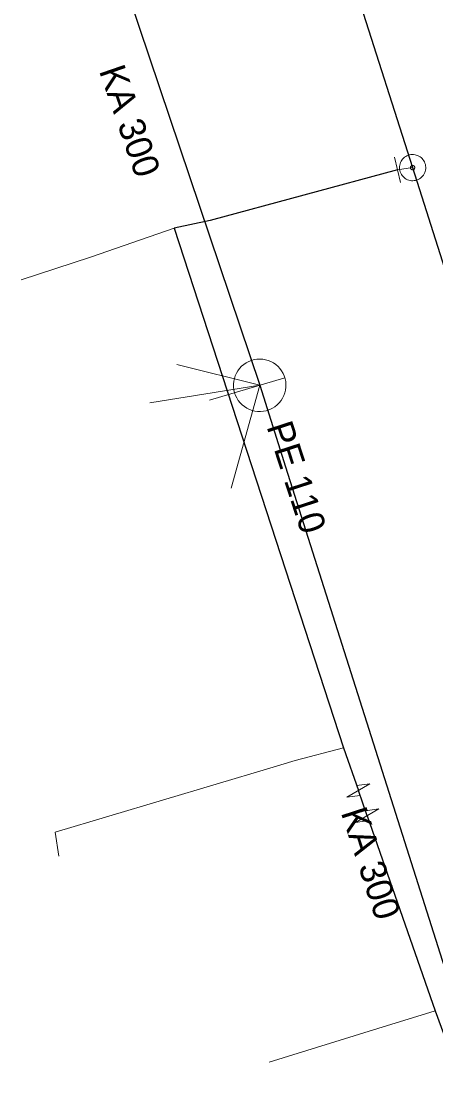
# Model space of a CAD drawing. Extents: x -807203 to -805207, y -993656 to -992505.
# Drawn here: x -807119.4 to -807103.6, y -993130.79 to -993090.44 of the extents above; entities that cross this region are included whole.
import ezdxf

# ---------------------------------------------------------------- set-up
doc = ezdxf.new("R2010")
doc.units = 0
doc.header["$LTSCALE"] = 0.4
for name, color, linetype, lineweight in [('1', 7, 'Continuous', 13), ('11', 7, 'Continuous', 13), ('13', 7, 'Continuous', 13), ('14', 7, 'Continuous', 25), ('17', 7, 'Continuous', 25), ('22', 7, 'Continuous', 13), ('34', 7, 'Continuous', 13), ('47', 7, 'Continuous', 13)]:
    doc.layers.add(name, color=color, linetype=linetype, lineweight=lineweight)

msp = doc.modelspace()

# ---------------------------------------------------------------- linework, layer by layer
at = {"layer": '11'}
for p in [(-807113.462, -993103.524), (-807114.492, -993104.983), (-807111.403, -993108.244)]:
    msp.add_line(p, (-807110.309, -993104.32), dxfattribs=at)
at = {"layer": '13'}
for points in [[(-807113.569, -993098.326), (-807116.755, -993099.441), (-807119.4, -993100.303)], [(-807107.119, -993118.131), (-807108.964, -993118.618), (-807109.93, -993118.915), (-807118.108, -993121.347), (-807117.97, -993122.264)], [(-807103.627, -993128.161), (-807105.804, -993128.827), (-807109.943, -993130.115)]]:
    msp.add_lwpolyline(points, dxfattribs=at)
at = {"layer": '14'}
msp.add_line((-807116.899, -993084.76), (-807110.309, -993104.32), dxfattribs=at)
at = {"layer": '14', "lineweight": 13}
msp.add_line((-807104.484, -993096.025), (-807105.057, -993096.108), dxfattribs=at)
at = {"layer": '14'}
msp.add_lwpolyline([(-807110.309, -993104.32), (-807109.321, -993107.433), (-807106.151, -993117.421), (-807099.532, -993138.273), (-807098.539, -993141.399)], dxfattribs=at)
at = {"layer": '17'}
for p, q in [((-807106.89, -993088.501), (-807104.484, -993096.025)), ((-807104.484, -993096.025), (-807102.744, -993101.5)), ((-807106.216, -993120.722), (-807106.549, -993119.766))]:
    msp.add_line(p, q, dxfattribs=at)
for points in [[(-807105.057, -993096.108), (-807112.196, -993098.04), (-807113.568, -993098.326), (-807107.118, -993118.131), (-807106.549, -993119.766)], [(-807106.216, -993120.722), (-807103.627, -993128.16), (-807102.219, -993132), (-807096.589, -993150.385), (-807096.195, -993151.629), (-807092.921, -993162.153), (-807079.791, -993202.059), (-807064.89, -993246.39), (-807059.596, -993262.052), (-807055.035, -993275.397), (-807053.806, -993278.989)]]:
    msp.add_lwpolyline(points, dxfattribs=at)
at = {"layer": '22'}
msp.add_line((-807112.226, -993104.889), (-807109.35, -993104.035), dxfattribs=at)
msp.add_lwpolyline([(-807110.024, -993105.278), (-807109.922, -993105.242), (-807109.823, -993105.194), (-807109.73, -993105.135), (-807109.645, -993105.068), (-807109.567, -993104.99), (-807109.498, -993104.905), (-807109.439, -993104.812), (-807109.391, -993104.715), (-807109.352, -993104.612), (-807109.326, -993104.506), (-807109.312, -993104.397), (-807109.31, -993104.287), (-807109.319, -993104.178), (-807109.341, -993104.071), (-807109.374, -993103.966), (-807109.418, -993103.866), (-807109.473, -993103.771), (-807109.537, -993103.683), (-807109.612, -993103.603), (-807109.694, -993103.531), (-807109.785, -993103.468), (-807109.88, -993103.416), (-807109.982, -993103.375), (-807110.087, -993103.344), (-807110.195, -993103.326), (-807110.304, -993103.32), (-807110.414, -993103.325), (-807110.522, -993103.343), (-807110.628, -993103.372), (-807110.729, -993103.413), (-807110.826, -993103.463), (-807110.916, -993103.526), (-807110.999, -993103.596), (-807111.075, -993103.676), (-807111.14, -993103.764), (-807111.196, -993103.858), (-807111.241, -993103.958), (-807111.275, -993104.062), (-807111.298, -993104.169), (-807111.308, -993104.278), (-807111.307, -993104.387), (-807111.293, -993104.496), (-807111.268, -993104.603), (-807111.231, -993104.706), (-807111.183, -993104.804), (-807111.126, -993104.897), (-807111.057, -993104.983), (-807110.98, -993105.061), (-807110.895, -993105.13), (-807110.803, -993105.189), (-807110.705, -993105.238), (-807110.602, -993105.276), (-807110.496, -993105.302), (-807110.388, -993105.316), (-807110.278, -993105.319), (-807110.168, -993105.31), (-807110.061, -993105.288)], close=True, dxfattribs=at)
at = {"layer": '34'}
msp.add_line((-807105.167, -993095.62), (-807104.947, -993096.595), dxfattribs=at)
at = {"layer": '47'}
for p, q in [((-807106.109, -993119.509), (-807106.615, -993119.576)), ((-807105.776, -993120.465), (-807106.282, -993120.532))]:
    msp.add_line(p, q, dxfattribs=at)
for points in [[(-807104.318, -993096.496), (-807104.269, -993096.476), (-807104.223, -993096.451), (-807104.181, -993096.421), (-807104.14, -993096.388), (-807104.104, -993096.35), (-807104.072, -993096.308), (-807104.045, -993096.264), (-807104.023, -993096.216), (-807104.005, -993096.168), (-807103.992, -993096.117), (-807103.985, -993096.064), (-807103.984, -993096.012), (-807103.988, -993095.96), (-807103.997, -993095.909), (-807104.012, -993095.859), (-807104.032, -993095.81), (-807104.057, -993095.764), (-807104.087, -993095.721), (-807104.12, -993095.681), (-807104.158, -993095.645), (-807104.2, -993095.613), (-807104.245, -993095.585), (-807104.292, -993095.563), (-807104.341, -993095.545), (-807104.391, -993095.533), (-807104.444, -993095.526), (-807104.496, -993095.524), (-807104.548, -993095.529), (-807104.599, -993095.538), (-807104.649, -993095.553), (-807104.698, -993095.573), (-807104.744, -993095.598), (-807104.788, -993095.627), (-807104.827, -993095.661), (-807104.863, -993095.699), (-807104.895, -993095.74), (-807104.923, -993095.785), (-807104.946, -993095.832), (-807104.963, -993095.882), (-807104.975, -993095.932), (-807104.982, -993095.985), (-807104.984, -993096.036), (-807104.979, -993096.089), (-807104.97, -993096.14), (-807104.955, -993096.19), (-807104.935, -993096.239), (-807104.91, -993096.285), (-807104.881, -993096.328), (-807104.847, -993096.368), (-807104.809, -993096.404), (-807104.768, -993096.436), (-807104.724, -993096.463), (-807104.676, -993096.486), (-807104.627, -993096.503), (-807104.576, -993096.516), (-807104.523, -993096.523), (-807104.472, -993096.524), (-807104.419, -993096.52), (-807104.368, -993096.511)], [(-807104.456, -993096.102), (-807104.448, -993096.099), (-807104.441, -993096.094), (-807104.434, -993096.09), (-807104.427, -993096.084), (-807104.421, -993096.078), (-807104.416, -993096.071), (-807104.411, -993096.064), (-807104.408, -993096.056), (-807104.405, -993096.048), (-807104.403, -993096.04), (-807104.402, -993096.031), (-807104.402, -993096.022), (-807104.402, -993096.014), (-807104.403, -993096.006), (-807104.406, -993095.997), (-807104.409, -993095.989), (-807104.414, -993095.982), (-807104.418, -993095.975), (-807104.424, -993095.968), (-807104.43, -993095.962), (-807104.437, -993095.957), (-807104.444, -993095.952), (-807104.452, -993095.949), (-807104.46, -993095.945), (-807104.468, -993095.944), (-807104.477, -993095.943), (-807104.486, -993095.943), (-807104.494, -993095.943), (-807104.502, -993095.944), (-807104.511, -993095.947), (-807104.519, -993095.95), (-807104.526, -993095.955), (-807104.533, -993095.959), (-807104.54, -993095.965), (-807104.546, -993095.971), (-807104.551, -993095.977), (-807104.556, -993095.985), (-807104.559, -993095.993), (-807104.563, -993096.001), (-807104.564, -993096.009), (-807104.565, -993096.018), (-807104.565, -993096.027), (-807104.565, -993096.035), (-807104.564, -993096.043), (-807104.561, -993096.052), (-807104.558, -993096.06), (-807104.553, -993096.067), (-807104.549, -993096.074), (-807104.543, -993096.081), (-807104.537, -993096.087), (-807104.531, -993096.092), (-807104.523, -993096.097), (-807104.515, -993096.1), (-807104.507, -993096.103), (-807104.499, -993096.105), (-807104.49, -993096.106), (-807104.481, -993096.106), (-807104.473, -993096.106), (-807104.465, -993096.105)]]:
    msp.add_lwpolyline(points, close=True, dxfattribs=at)
for points in [[(-807106.109, -993119.509), (-807106.988, -993120.022), (-807106.482, -993119.955)], [(-807105.776, -993120.465), (-807106.655, -993120.978), (-807106.149, -993120.911)]]:
    msp.add_lwpolyline(points, dxfattribs=at)

# ---------------------------------------------------------------- texts
at = {"layer": '1'}
for s, rotation, p in [('KA 300', 289, (-807116.443, -993092.33)), ('PE 110', 288, (-807110.055, -993105.888)), ('KA 300', 288, (-807107.224, -993120.6))]:
    msp.add_text(s, height=1, rotation=rotation, dxfattribs=at).set_placement(p)

doc.saveas('drawing.dxf')
